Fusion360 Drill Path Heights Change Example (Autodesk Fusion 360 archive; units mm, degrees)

design "TourDisc_BasePlate_Rods" references "hardPoint"
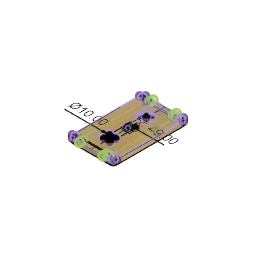
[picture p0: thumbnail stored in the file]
parameter "guideRingDepth" = -5 comment "To be Updated"
parameter "diskHeight_Ref" = 40
parameter "diskCutDepth_Ref" = 20
parameter "sinkDepthTube_Ref" = 15
parameter "maxMillingDepth_Ref" = 20
parameter "drillDiameter_Ref" = 5
parameter "tubeWidth_Ref" = 50
parameter "drillRadius" = 5 comment "To be Updated"
parameter "d63" = 0 comment "To be Updated"
parameter "tubeCopySlotWidth" = 10 comment "To be Update"
external_derived "baseSketch"
derived_instance "DerivedInstance2"
sketch "baseSketch" plane through (0, 0, 0) normal (0, 0, 1) x axis (1, 0, 0)
  line L1 (-150, 250) -> (150, 250)
  line L2 (-150, -250) -> (-150, 250)
  line L3 (150, -250) -> (-150, -250)
  line L4 (150, 250) -> (150, -250)
  line L5 (-150, -250) -> (150, 250)
  line L6 (150, -250) -> (-150, 250)
  point P6 (0, 0)
  point P1 (0, 0)
  point P2 (150, 250)
  point P5 (150, -250)
  point P3 (-150, 250)
  horizontal L1
  perpendicular L1 L2
  parallel L1 L3
  parallel L2 L4
  coincident L5 P6
  coincident L6 P6
  coincident P1 P6
  dimension "baseLength" distance P2 P5 = 500
  dimension "baseWidth" distance P2 P3 = 300
extrude "Extrude1" new body sketch "baseSketch" profile of L1 L2 L3 L4 against normal blind 30 named "baseThickness"
fillet "Fillet3" radius 20 named "baseRounding"
sketch "tubeSinkSketch" plane through (0, 0, 0) normal (0, 0, 1) x axis (-1, 0, 0)
  line L1 (-100, -230) -> (-100, 230)
  line L2 (-80, 250) -> (80, 250)
  line L3 (100, 230) -> (100, -230)
  line L4 (80, -250) -> (-80, -250)
  line L5 (24.5, 149.5) -> (-24.5, 149.5)
  line L6 (24.5, 100.5) -> (24.5, 149.5)
  line L7 (-24.5, 100.5) -> (24.5, 100.5)
  line L8 (-24.5, 149.5) -> (-24.5, 100.5)
  line L9 (24.5, 100.5) -> (-24.5, 149.5)
  line L10 (-24.5, 100.5) -> (24.5, 149.5)
  line L11 (0, 125) -> (0, 0)
  line L12 (0, 250) -> (0, 125)
  line L13 (150, 230) -> (150, -230)
  line L14 (-130, 250) -> (130, 250)
  line L15 (-150, -230) -> (-150, 230)
  line L16 (130, -250) -> (-130, -250)
  line L17 (-19.5, 105.5) -> (19.5, 105.5)
  line L18 (-19.5, 144.5) -> (-19.5, 105.5)
  line L19 (19.5, 144.5) -> (-19.5, 144.5)
  line L20 (19.5, 105.5) -> (19.5, 144.5)
  arc A1 centre (80, 230) radius 20 clockwise from (80, 250) to (100, 230)
  arc A2 centre (80, -230) radius 20 clockwise from (100, -230) to (80, -250)
  arc A3 centre (-80, -230) radius 20 clockwise from (-80, -250) to (-100, -230)
  arc A4 centre (-80, 230) radius 20 clockwise from (-100, 230) to (-80, 250)
  arc A5 centre (130, -230) radius 20 clockwise from (150, -230) to (130, -250)
  arc A6 centre (130, 230) radius 20 clockwise from (130, 250) to (150, 230)
  arc A7 centre (-130, 230) radius 20 clockwise from (-150, 230) to (-130, 250)
  arc A8 centre (-130, -230) radius 20 clockwise from (-130, -250) to (-150, -230)
  circle C1 centre (19.5, 105.5) radius 5
  circle C2 centre (-19.5, 105.5) radius 5
  circle C3 centre (-19.5, 144.5) radius 5
  circle C4 centre (19.5, 144.5) radius 5
  point P10 (0, 125)
  point P1 (0, 0)
  point P11 (0, 0)
  point P12 (0, 125)
  point P13 (0, 125)
  point P14 (0, 250)
  point P41 (19.5, 105.5)
  point P42 (-19.5, 105.5)
  point P43 (-19.5, 144.5)
  point P44 (19.5, 144.5)
  point P47 (-19.5, 144.5)
  point P45 (19.5, 105.5)
  point P48 (19.5, 144.5)
  point P46 (-19.5, 105.5)
  point P8 (24.5, 100.5)
  point P9 (-24.5, 100.5)
  horizontal L5
  perpendicular L5 L6
  parallel L5 L7
  parallel L6 L8
  coincident L9 P10
  coincident L10 P10
  coincident P1 P11
  coincident P10 P12
  coincident P10 P13
  midpoint L2 P14
  vertical L12
  equal L11 L12
  equal L7 L8
  coincident L9 P41
  coincident L10 P42
  coincident L9 P43
  coincident L10 P44
  horizontal L17
  vertical L18
  horizontal L19
  vertical L20
  coincident P43 P47
  coincident P41 P45
  coincident P44 P48
  coincident P42 P46
  equal C1 C2
  equal C2 C3
  equal C3 C4
  tangent L7 C1
  dimension "mountHoleOuterSize" distance P8 P9 = 49 (= "tubeWidth_Ref - 1 mm")
  dimension "rodDiameter" diameter C1 = 10
extrude "Extrude17" cut sketch "tubeSinkSketch" profile of C1 C2 C3 C4 no distance stored
sketch "Sketch16" plane through (0, 0, 0) normal (0, 0, 1) x axis (-1, 0, 0)
  line L1 (150, 230) -> (150, -230)
  line L2 (-130, 250) -> (130, 250)
  line L3 (-150, -230) -> (-150, 230)
  line L4 (130, -250) -> (-130, -250)
  line L5 (0, -250) -> (0, 0)
  line L6 (25, -150) -> (-25, -150)
  line L7 (25, -100) -> (25, -150)
  line L8 (-25, -100) -> (25, -100)
  line L9 (-25, -150) -> (-25, -100)
  line L10 (25, -100) -> (-25, -150)
  line L11 (-25, -100) -> (25, -150)
  circle C1 centre (-19.5, 105.5) radius 5
  circle C2 centre (-19.5, 144.5) radius 5
  circle C3 centre (19.5, 105.5) radius 5
  circle C4 centre (19.5, 144.5) radius 5
  arc A1 centre (130, -230) radius 20 clockwise from (150, -230) to (130, -250)
  arc A2 centre (130, 230) radius 20 clockwise from (130, 250) to (150, 230)
  arc A3 centre (-130, 230) radius 20 clockwise from (-150, 230) to (-130, 250)
  arc A4 centre (-130, -230) radius 20 clockwise from (-130, -250) to (-150, -230)
  point P1 (0, 0)
  point P18 (0, 0)
  point P19 (0, -250)
  point P24 (0, -125)
  point P20 (-25, -150)
  point P21 (25, -150)
  coincident P1 P18
  midpoint L4 P19
  horizontal L6
  perpendicular L6 L7
  parallel L6 L8
  parallel L7 L9
  coincident L10 P24
  coincident L11 P24
  midpoint L5 P24
  equal L6 L9
  dimension "tubeDiameter2" distance P20 P21 = 50
work_plane "WorkPlane1" RotateAngle 0 named "tubeAngle"
sketch "Sketch17" plane through (0, 125, 0) normal (0, 0, 1) x axis (-0.7071, -0.7071, 0)
  line L1 (-35.3553, 0) -> (0, 35.3553)
  line L2 (0, 35.3553) -> (35.3553, 0)
  line L3 (0, 35.3553) -> (0, -35.3553)
  circle C1 centre (0, 28.2843) radius 5
  point P8 (0, 28.2843)
  coincident L3 P8
  tangent L1 C1
  dimension "angleHoleDiameter" diameter C1 = 10
extrude "Extrude18" cut sketch "Sketch17" profile of C1 no distance stored
work_axis "WorkAxis1"
circular_pattern "C-Pattern1" TotalAngle 360
sketch "slotSketch" plane through (0, 0, 0) normal (0, 0, 1) x axis (-1, 0, 0)
  line L1 (150, 230) -> (150, -230)
  line L2 (-130, 250) -> (130, 250)
  line L3 (-150, -230) -> (-150, 230)
  line L4 (130, -250) -> (-130, -250)
  line L5 (100.0011, 215.95) -> (-100.0032, 215.95)
  line L6 (100.0011, 224.05) -> (100.0011, 215.95)
  line L7 (-99.9989, 224.05) -> (100.0011, 224.05)
  line L8 (100.0011, 224.05) -> (-100.0032, 215.95)
  line L9 (-99.9989, 224.05) -> (100.0011, 215.95)
  line L10 (0, 220) -> (0, 250)
  line L11 (-99.9989, 224.05) -> (-100.0032, 215.95)
  arc A1 centre (130, -230) radius 20 clockwise from (150, -230) to (130, -250)
  arc A2 centre (130, 230) radius 20 clockwise from (130, 250) to (150, 230)
  arc A3 centre (-130, 230) radius 20 clockwise from (-150, 230) to (-130, 250)
  arc A4 centre (-130, -230) radius 20 clockwise from (-130, -250) to (-150, -230)
  arc A5 centre (-100.0032, 220) radius 4.05 clockwise from (-100.0032, 215.95) to (-99.9989, 224.05)
  arc A6 centre (100.0011, 220) radius 4.05 clockwise from (100.0011, 224.05) to (100.0011, 215.95)
  circle C1 centre (-19.5, 105.5) radius 5
  circle C2 centre (-19.5, 144.5) radius 5
  circle C3 centre (19.5, 105.5) radius 5
  circle C4 centre (19.5, 144.5) radius 5
  circle C5 centre (20, -105) radius 5
  circle C6 centre (20, -145) radius 5
  circle C7 centre (-20, -145) radius 5
  circle C8 centre (-20, -105) radius 5
  point P18 (0, 220)
  point P19 (0, 250)
  point P20 (0, 220)
  point P14 (-100.0032, 215.95)
  point P17 (-99.9989, 224.05)
  point P16 (100.0011, 224.05)
  horizontal L5
  perpendicular L5 L6
  parallel L5 L7
  coincident L8 P18
  coincident L9 P18
  midpoint L2 P19
  coincident P18 P20
  vertical L10
  tangent L5 A5
  tangent L5 A6
  dimension "slotWidth" distance P14 P17 = 8.1
  dimension "slotLength" distance P16 P17 = 200 (= "( baseWidth * 2 ) / 3")
  dimension "slotOffset" distance P19 P20 = 30
extrude "Extrude12" cut sketch "slotSketch" profile of L5 L7 A5 A6 to an object
mirror "Mirror5" mirrorStitchTolerance 0.1
sketch "originHoleSketch" plane through (0, 0, 0) normal (0, 0, 1) x axis (-1, 0, 0)
  line L1 (150, 230) -> (150, -230)
  line L2 (-130, 250) -> (130, 250)
  line L3 (-150, -230) -> (-150, 230)
  line L4 (130, -250) -> (-130, -250)
  line L5 (-100.0032, 215.95) -> (100.0011, 215.95)
  line L6 (100.0011, 224.05) -> (-99.9989, 224.05)
  line L7 (-99.9989, -224.05) -> (100.0011, -224.05)
  line L8 (100.0011, -215.95) -> (-100.0032, -215.95)
  curve K1
  arc A1 centre (130, -230) radius 20 clockwise from (150, -230) to (130, -250)
  arc A2 centre (130, 230) radius 20 clockwise from (130, 250) to (150, 230)
  arc A3 centre (-130, 230) radius 20 clockwise from (-150, 230) to (-130, 250)
  arc A4 centre (-130, -230) radius 20 clockwise from (-130, -250) to (-150, -230)
  circle C1 centre (0, 0) radius 3
  arc A5 centre (-100.0032, 220) radius 4.05 clockwise from (-100.0032, 215.95) to (-99.9989, 224.05)
  arc A6 centre (100.0011, 220) radius 4.05 clockwise from (100.0011, 224.05) to (100.0011, 215.95)
  circle C2 centre (-19.5, 105.5) radius 5
  circle C3 centre (-19.5, 144.5) radius 5
  circle C4 centre (19.5, 105.5) radius 5
  circle C5 centre (19.5, 144.5) radius 5
  arc A7 centre (-100.0032, -220) radius 4.05 clockwise from (-99.9989, -224.05) to (-100.0032, -215.95)
  arc A8 centre (100.0011, -220) radius 4.05 clockwise from (100.0011, -215.95) to (100.0011, -224.05)
  circle C6 centre (20, -105) radius 5
  circle C7 centre (20, -145) radius 5
  circle C8 centre (-20, -145) radius 5
  circle C9 centre (-20, -105) radius 5
  point P1 (0, 0)
  point P14 (0, 0)
  coincident P1 P14
  dimension "calPointDiameter" diameter C1 = 6
extrude "Extrude16" cut sketch "originHoleSketch" profile of C1 against normal blind 7 named "callPointDepth"
rectangular_pattern "R-Pattern3" uSpaceDistance 25 named "d72" vSpaceDistance 25 (= "d72")
sketch "originText" plane through (0, 0, 0) normal (0, 0, 1) x axis (-1, 0, 0)
  line L1 (-100.0032, 215.95) -> (100.0011, 215.95)
  line L2 (100.0011, 224.05) -> (-99.9989, 224.05)
  line L3 (150, 230) -> (150, -230)
  line L4 (-130, 250) -> (130, 250)
  line L5 (-150, -230) -> (-150, 230)
  line L6 (130, -250) -> (-130, -250)
  curve K1
  curve K2
  curve K3
  curve K4
  line L7 (-25, 0) -> (0, 0)
  line L8 (-25, -25) -> (-25, 0)
  line L9 (0, -25) -> (-25, -25)
  line L10 (0, 0) -> (0, -25)
  line L11 (-25, 15) -> (-25, 0)
  line L12 (0, 15) -> (-25, 15)
  line L13 (0, 0) -> (0, 15)
  line L14 (0, -25) -> (15, -25)
  line L15 (15, 0) -> (0, 0)
  line L16 (15, -25) -> (15, 0)
  curve K5
  curve K6
  curve K7
  curve K8
  curve K9
  curve K10
  curve K11
  curve K12
  line L17 (-99.9989, -224.05) -> (100.0011, -224.05)
  line L18 (100.0011, -215.95) -> (-100.0032, -215.95)
  curve K13
  curve K14
  curve K15
  curve K16
  curve K17
  curve K18
  curve K19
  curve K20
  curve K21
  curve K22
  circle C1 centre (-25, -25) radius 3
  circle C2 centre (0, -25) radius 3
  circle C3 centre (-25, 0) radius 3
  circle C4 centre (0, 0) radius 3
  arc A1 centre (-100.0032, 220) radius 4.05 clockwise from (-100.0032, 215.95) to (-99.9989, 224.05)
  arc A2 centre (100.0011, 220) radius 4.05 clockwise from (100.0011, 224.05) to (100.0011, 215.95)
  arc A3 centre (130, -230) radius 20 clockwise from (150, -230) to (130, -250)
  arc A4 centre (130, 230) radius 20 clockwise from (130, 250) to (150, 230)
  arc A5 centre (-130, 230) radius 20 clockwise from (-150, 230) to (-130, 250)
  arc A6 centre (-130, -230) radius 20 clockwise from (-130, -250) to (-150, -230)
  circle C5 centre (-19.5, 105.5) radius 5
  circle C6 centre (-19.5, 144.5) radius 5
  circle C7 centre (19.5, 105.5) radius 5
  circle C8 centre (19.5, 144.5) radius 5
  arc A7 centre (-100.0032, -220) radius 4.05 clockwise from (-99.9989, -224.05) to (-100.0032, -215.95)
  arc A8 centre (100.0011, -220) radius 4.05 clockwise from (100.0011, -215.95) to (100.0011, -224.05)
  circle C9 centre (20, -105) radius 5
  circle C10 centre (20, -145) radius 5
  circle C11 centre (-20, -145) radius 5
  circle C12 centre (-20, -105) radius 5
  point P2 (-25, -25)
  point P26 (-25, -25)
  point P5 (0, 0)
  point P24 (0, 0)
  point P28 (0, 0)
  point P30 (0, 15)
  point P32 (0, 0)
  point P29 (-25, 15)
  point P31 (15, -25)
  point P25 (-25, 0)
  horizontal L7
  vertical L8
  horizontal L9
  vertical L10
  coincident P2 P26
  coincident P5 P24
  vertical L11
  horizontal L12
  vertical L13
  horizontal L14
  horizontal L15
  vertical L16
  coincident P5 P28
  coincident P30
  horizontal K1
  coincident P5 P32
  coincident P29
  coincident P31
  horizontal K9
  horizontal K5
  equal K1 K4
  equal K4 K8
  equal K5 K8
  equal K5 K9
  equal K9 K12
  equal K1 L12
  equal L13 L15
  dimension "textOffset" distance P25 P29 = 15
work_axis "WorkAxis2" sketch "tubeSinkSketch"
work_axis "WorkAxis4"
work_axis "WorkAxis5"
work_axis "WorkAxis6"
work_axis "WorkAxis7"
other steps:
derived_base_feature "Derived Base Feature"
create_component "CreateComponent2"

design "hardPoint"
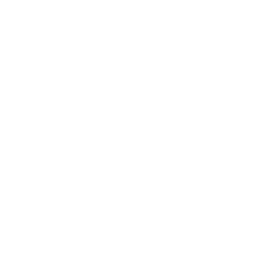
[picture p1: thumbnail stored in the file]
parameter "diskHeight" = 40
parameter "diskCutDepth" = 20
parameter "sinkDepthTube" = 15
parameter "maxMillingDepth" = 20
parameter "drillDiameter" = 5
parameter "tubeWidth" = 50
